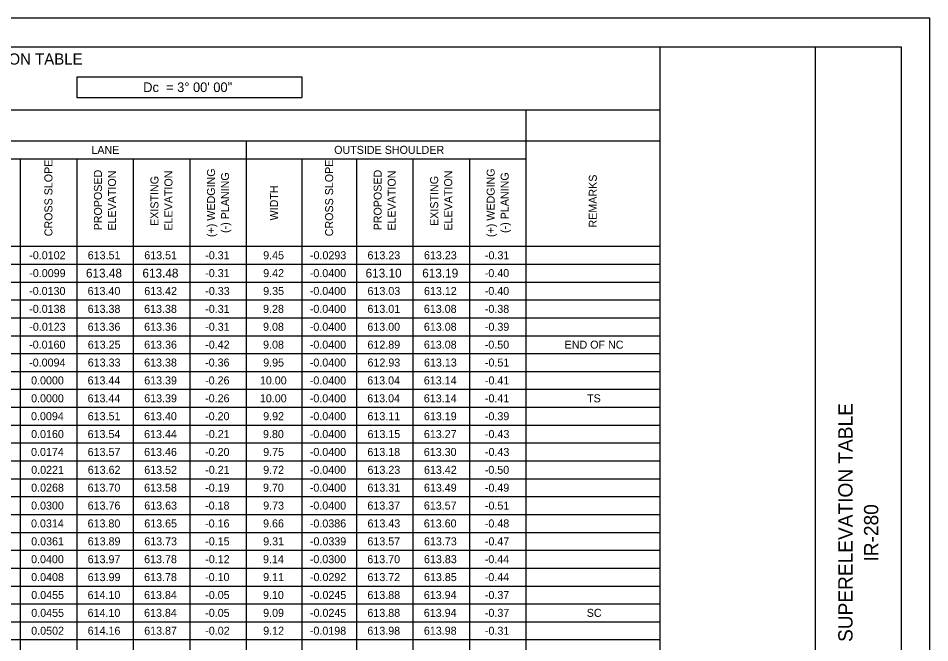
# Model space of a CAD drawing. Extents: x 0 to 34, y 0 to 22.
# Drawn here: x 18.06 to 34, y 11.07 to 22 of the extents above; entities that cross this region are included whole.
import ezdxf

# ---------------------------------------------------------------- set-up
doc = ezdxf.new("R2010")
doc.units = 0
for name, color, linetype in [('SH_Border', 7, 'Continuous'), ('SH_Cut_Line', 7, 'Continuous'), ('SH_Data', 7, 'Continuous'), ('SH_Text', 7, 'Continuous')]:
    doc.layers.add(name, color=color, linetype=linetype)

msp = doc.modelspace()

# ---------------------------------------------------------------- linework, layer by layer
at = {"layer": 'SH_Border'}
msp.add_line((32, 0.5), (32, 21.5), dxfattribs=at)
msp.add_lwpolyline([(1.5, 21.5), (33.5, 21.5), (33.5, 0.5), (1.5, 0.5)], close=True, dxfattribs=at)
at = {"layer": 'SH_Cut_Line'}
msp.add_lwpolyline([(0, 0), (34, 0), (34, 22), (0, 22)], close=True, dxfattribs=at)
at = {"layer": 'SH_Text'}
for p, q in [((26.938, 21.5), (29.277, 21.5)), ((29.277, 21.5), (29.277, 0.484)), ((19.081, 20.973), (23.018, 20.973)), ((19.081, 20.973), (19.081, 20.611)), ((23.018, 20.973), (23.018, 20.611)), ((19.081, 20.611), (23.018, 20.611)), ((4.225, 20.396), (29.277, 20.396)), ((26.938, 20.396), (26.938, 0.484)), ((4.225, 19.853), (29.277, 19.853)), ((22.046, 19.853), (22.046, 0.484)), ((6.3, 19.54), (26.938, 19.54)), ((18.093, 19.54), (18.093, 0.484)), ((19.081, 19.54), (19.081, 0.484)), ((20.07, 19.54), (20.07, 0.484)), ((21.058, 19.54), (21.058, 0.484)), ((23.018, 19.54), (23.018, 0.484)), ((23.973, 19.54), (23.973, 0.484)), ((24.961, 19.54), (24.961, 0.484)), ((25.95, 19.54), (25.95, 0.484)), ((4.225, 18.008), (29.277, 18.008)), ((4.225, 17.695), (29.277, 17.695)), ((4.225, 17.382), (29.277, 17.382)), ((4.225, 17.069), (29.277, 17.069)), ((4.225, 16.756), (29.277, 16.756)), ((4.225, 16.444), (29.277, 16.444)), ((4.225, 16.131), (29.277, 16.131)), ((4.225, 15.818), (29.277, 15.818)), ((4.225, 15.505), (29.277, 15.505)), ((4.225, 15.192), (29.277, 15.192)), ((4.225, 14.879), (29.277, 14.879)), ((4.225, 14.566), (29.277, 14.566)), ((4.225, 14.253), (29.277, 14.253)), ((4.225, 13.94), (29.277, 13.94)), ((4.225, 13.627), (29.277, 13.627)), ((4.225, 13.314), (29.277, 13.314)), ((4.225, 13.001), (29.277, 13.001)), ((4.225, 12.688), (29.277, 12.688)), ((4.225, 12.375), (29.277, 12.375)), ((4.225, 12.062), (29.277, 12.062)), ((4.225, 11.749), (29.277, 11.749)), ((4.225, 11.436), (29.277, 11.436)), ((4.225, 11.124), (29.277, 11.124))]:
    msp.add_line(p, q, dxfattribs=at)

# ---------------------------------------------------------------- texts
at = {"layer": 'SH_Data'}
for s, p in [('SUPERELEVATION TABLE', (32.65, 11.084)), ('IR-280', (33.1, 12.491))]:
    msp.add_text(s, height=0.25, rotation=90, dxfattribs=at).set_placement(p)
at = {"layer": 'SH_Text'}
for s, height, p in [('WOO/LUC-280-06.20/00.00 - SUPERELEVATION TABLE', 0.196, (12.425, 21.188)), ('Dc  = 3° 00\' 00"', 0.168, (20.245, 20.708)), ('OUTSIDE SHOULDER', 0.14, (23.584, 19.626)), ('LANE', 0.14, (19.338, 19.626)), ('-0.0102', 0.14, (18.252, 17.782)), ('613.51', 0.14, (19.274, 17.782)), ('613.51', 0.14, (20.263, 17.782)), ('-0.31', 0.14, (21.329, 17.782)), ('9.45', 0.14, (22.343, 17.782)), ('-0.0293', 0.14, (23.161, 17.782)), ('613.23', 0.14, (24.167, 17.782)), ('613.23', 0.14, (25.155, 17.782)), ('-0.31', 0.14, (26.221, 17.782)), ('-0.0099', 0.14, (18.252, 17.469)), ('613.48', 0.154, (19.243, 17.462)), ('613.48', 0.154, (20.231, 17.462)), ('-0.31', 0.14, (21.329, 17.469)), ('9.42', 0.14, (22.343, 17.469)), ('-0.0400', 0.14, (23.158, 17.469)), ('613.10', 0.154, (24.134, 17.462)), ('613.19', 0.154, (25.124, 17.462)), ('-0.40', 0.14, (26.218, 17.469)), ('-0.0130', 0.14, (18.25, 17.156)), ('613.40', 0.14, (19.272, 17.156)), ('613.42', 0.14, (20.263, 17.156)), ('-0.33', 0.14, (21.33, 17.156)), ('9.35', 0.14, (22.343, 17.156)), ('-0.0400', 0.14, (23.158, 17.156)), ('613.03', 0.14, (24.167, 17.156)), ('613.12', 0.14, (25.155, 17.156)), ('-0.40', 0.14, (26.218, 17.156)), ('-0.0138', 0.14, (18.251, 16.843)), ('613.38', 0.14, (19.273, 16.843)), ('613.38', 0.14, (20.261, 16.843)), ('-0.31', 0.14, (21.329, 16.843)), ('9.28', 0.14, (22.341, 16.843)), ('-0.0400', 0.14, (23.158, 16.843)), ('613.01', 0.14, (24.166, 16.843)), ('613.08', 0.14, (25.153, 16.843)), ('-0.38', 0.14, (26.219, 16.843)), ('-0.0123', 0.14, (18.253, 16.53)), ('613.36', 0.14, (19.273, 16.53)), ('613.36', 0.14, (20.261, 16.53)), ('-0.31', 0.14, (21.329, 16.53)), ('9.08', 0.14, (22.341, 16.53)), ('-0.0400', 0.14, (23.158, 16.53)), ('613.00', 0.14, (24.164, 16.53)), ('613.08', 0.14, (25.153, 16.53)), ('-0.39', 0.14, (26.22, 16.53)), ('-0.0160', 0.14, (18.25, 16.217)), ('613.25', 0.14, (19.275, 16.217)), ('613.36', 0.14, (20.261, 16.217)), ('-0.42', 0.14, (21.329, 16.217)), ('9.08', 0.14, (22.341, 16.217)), ('-0.0400', 0.14, (23.158, 16.217)), ('612.89', 0.14, (24.166, 16.217)), ('613.08', 0.14, (25.153, 16.217)), ('-0.50', 0.14, (26.218, 16.217)), ('END OF NC', 0.14, (27.614, 16.217)), ('-0.0094', 0.14, (18.25, 15.904)), ('613.33', 0.14, (19.275, 15.904)), ('613.38', 0.14, (20.261, 15.904)), ('-0.36', 0.14, (21.327, 15.904)), ('9.95', 0.14, (22.343, 15.904)), ('-0.0400', 0.14, (23.158, 15.904)), ('612.93', 0.14, (24.167, 15.904)), ('613.13', 0.14, (25.155, 15.904)), ('-0.51', 0.14, (26.221, 15.904)), ('0.0000', 0.14, (18.284, 15.591)), ('613.44', 0.14, (19.272, 15.591)), ('613.39', 0.14, (20.262, 15.591)), ('-0.26', 0.14, (21.327, 15.591)), ('10.00', 0.14, (22.285, 15.591)), ('-0.0400', 0.14, (23.158, 15.591)), ('613.04', 0.14, (24.163, 15.591)), ('613.14', 0.14, (25.152, 15.591)), ('-0.41', 0.14, (26.221, 15.591)), ('0.0000', 0.14, (18.284, 15.278)), ('613.44', 0.14, (19.272, 15.278)), ('613.39', 0.14, (20.262, 15.278)), ('-0.26', 0.14, (21.327, 15.278)), ('10.00', 0.14, (22.285, 15.278)), ('-0.0400', 0.14, (23.158, 15.278)), ('613.04', 0.14, (24.163, 15.278)), ('613.14', 0.14, (25.152, 15.278)), ('-0.41', 0.14, (26.221, 15.278)), ('TS', 0.14, (28.007, 15.278)), ('0.0094', 0.14, (18.283, 14.965)), ('613.51', 0.14, (19.274, 14.965)), ('613.40', 0.14, (20.26, 14.965)), ('-0.20', 0.14, (21.327, 14.965)), ('9.92', 0.14, (22.343, 14.965)), ('-0.0400', 0.14, (23.158, 14.965)), ('613.11', 0.14, (24.166, 14.965)), ('613.19', 0.14, (25.154, 14.965)), ('-0.39', 0.14, (26.22, 14.965)), ('0.0160', 0.14, (18.284, 14.652)), ('613.54', 0.14, (19.272, 14.652)), ('613.44', 0.14, (20.26, 14.652)), ('-0.21', 0.14, (21.329, 14.652)), ('9.80', 0.14, (22.34, 14.652)), ('-0.0400', 0.14, (23.158, 14.652)), ('613.15', 0.14, (24.167, 14.652)), ('613.27', 0.14, (25.153, 14.652)), ('-0.43', 0.14, (26.221, 14.652)), ('0.0174', 0.14, (18.283, 14.339)), ('613.57', 0.14, (19.273, 14.339)), ('613.46', 0.14, (20.261, 14.339)), ('-0.20', 0.14, (21.327, 14.339)), ('9.75', 0.14, (22.343, 14.339)), ('-0.0400', 0.14, (23.158, 14.339)), ('613.18', 0.14, (24.165, 14.339)), ('613.30', 0.14, (25.152, 14.339)), ('-0.43', 0.14, (26.221, 14.339)), ('0.0221', 0.14, (18.286, 14.026)), ('613.62', 0.14, (19.275, 14.026)), ('613.52', 0.14, (20.263, 14.026)), ('-0.21', 0.14, (21.329, 14.026)), ('9.72', 0.14, (22.343, 14.026)), ('-0.0400', 0.14, (23.158, 14.026)), ('613.23', 0.14, (24.167, 14.026)), ('613.42', 0.14, (25.155, 14.026)), ('-0.50', 0.14, (26.218, 14.026)), ('0.0268', 0.14, (18.285, 13.714)), ('613.70', 0.14, (19.272, 13.714)), ('613.58', 0.14, (20.261, 13.714)), ('-0.19', 0.14, (21.328, 13.714)), ('9.70', 0.14, (22.34, 13.714)), ('-0.0400', 0.14, (23.158, 13.714)), ('613.31', 0.14, (24.166, 13.714)), ('613.49', 0.14, (25.154, 13.714)), ('-0.49', 0.14, (26.22, 13.714)), ('0.0300', 0.14, (18.284, 13.401)), ('613.76', 0.14, (19.273, 13.401)), ('613.63', 0.14, (20.263, 13.401)), ('-0.18', 0.14, (21.327, 13.401)), ('9.73', 0.14, (22.343, 13.401)), ('-0.0400', 0.14, (23.158, 13.401)), ('613.37', 0.14, (24.165, 13.401)), ('613.57', 0.14, (25.153, 13.401)), ('-0.51', 0.14, (26.221, 13.401)), ('0.0314', 0.14, (18.283, 13.088)), ('613.80', 0.14, (19.272, 13.088)), ('613.65', 0.14, (20.263, 13.088)), ('-0.16', 0.14, (21.327, 13.088)), ('9.66', 0.14, (22.341, 13.088)), ('-0.0386', 0.14, (23.159, 13.088)), ('613.43', 0.14, (24.167, 13.088)), ('613.60', 0.14, (25.152, 13.088)), ('-0.48', 0.14, (26.219, 13.088)), ('0.0361', 0.14, (18.286, 12.775)), ('613.89', 0.14, (19.274, 12.775)), ('613.73', 0.14, (20.263, 12.775)), ('-0.15', 0.14, (21.329, 12.775)), ('9.31', 0.14, (22.343, 12.775)), ('-0.0339', 0.14, (23.16, 12.775)), ('613.57', 0.14, (24.165, 12.775)), ('613.73', 0.14, (25.155, 12.775)), ('-0.47', 0.14, (26.22, 12.775)), ('0.0400', 0.14, (18.284, 12.462)), ('613.97', 0.14, (19.273, 12.462)), ('613.78', 0.14, (20.261, 12.462)), ('-0.12', 0.14, (21.329, 12.462)), ('9.14', 0.14, (22.34, 12.462)), ('-0.0300', 0.14, (23.158, 12.462)), ('613.70', 0.14, (24.164, 12.462)), ('613.83', 0.14, (25.155, 12.462)), ('-0.44', 0.14, (26.218, 12.462)), ('0.0408', 0.14, (18.285, 12.149)), ('613.99', 0.14, (19.274, 12.149)), ('613.78', 0.14, (20.261, 12.149)), ('-0.10', 0.14, (21.327, 12.149)), ('9.11', 0.14, (22.343, 12.149)), ('-0.0292', 0.14, (23.161, 12.149)), ('613.72', 0.14, (24.166, 12.149)), ('613.85', 0.14, (25.155, 12.149)), ('-0.44', 0.14, (26.218, 12.149)), ('0.0455', 0.14, (18.287, 11.836)), ('614.10', 0.14, (19.272, 11.836)), ('613.84', 0.14, (20.26, 11.836)), ('-0.05', 0.14, (21.329, 11.836)), ('9.10', 0.14, (22.34, 11.836)), ('-0.0245', 0.14, (23.161, 11.836)), ('613.88', 0.14, (24.165, 11.836)), ('613.94', 0.14, (25.152, 11.836)), ('-0.37', 0.14, (26.22, 11.836)), ('0.0455', 0.14, (18.287, 11.523)), ('614.10', 0.14, (19.272, 11.523)), ('613.84', 0.14, (20.26, 11.523)), ('-0.05', 0.14, (21.329, 11.523)), ('9.09', 0.14, (22.342, 11.523)), ('-0.0245', 0.14, (23.161, 11.523)), ('613.88', 0.14, (24.165, 11.523)), ('613.94', 0.14, (25.152, 11.523)), ('-0.37', 0.14, (26.22, 11.523)), ('SC', 0.14, (28.001, 11.523)), ('0.0502', 0.14, (18.286, 11.21)), ('614.16', 0.14, (19.273, 11.21)), ('613.87', 0.14, (20.262, 11.21)), ('-0.02', 0.14, (21.329, 11.21)), ('9.12', 0.14, (22.343, 11.21)), ('-0.0198', 0.14, (23.159, 11.21)), ('613.98', 0.14, (24.165, 11.21)), ('613.98', 0.14, (25.153, 11.21)), ('-0.31', 0.14, (26.221, 11.21))]:
    msp.add_text(s, height=height, dxfattribs=at).set_placement(p)
for s, p in [('CROSS SLOPE', (18.657, 18.183)), ('CROSS SLOPE', (23.566, 18.183)), ('PROPOSED ', (19.523, 18.287)), ('ELEVATION', (19.768, 18.283)), ('ELEVATION', (20.756, 18.283)), ('(+) WEDGING', (21.5, 18.17)), ('(-) PLANING', (21.745, 18.242)), ('PROPOSED ', (24.415, 18.287)), ('ELEVATION', (24.66, 18.283)), ('ELEVATION', (25.648, 18.283)), ('(+) WEDGING', (26.391, 18.17)), ('(-) PLANING', (26.636, 18.242)), ('EXISTING ', (20.511, 18.365)), ('EXISTING ', (25.403, 18.365)), ('REMARKS', (28.177, 18.337)), ('WIDTH', (22.602, 18.461))]:
    msp.add_text(s, height=0.14, rotation=90, dxfattribs=at).set_placement(p)

doc.saveas('drawing.dxf')
